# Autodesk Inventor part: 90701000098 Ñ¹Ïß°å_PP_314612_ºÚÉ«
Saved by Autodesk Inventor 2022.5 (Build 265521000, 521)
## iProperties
Created: 2024-07
Part Number: 90701000098 Ñ¹Ïß°å_PP_314612_ºÚÉ«
Material: Generic
Document SubType Name: Modeling
Designer: AdminForWorker
Density: 1 g/cm^3
Appearance: Default
Title: 90701000098 Ñ¹Ïß°å_PP_314612_ºÚÉ«
Author: AdminForWorker
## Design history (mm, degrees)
feature "Body1"
body "Solid1"
